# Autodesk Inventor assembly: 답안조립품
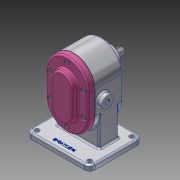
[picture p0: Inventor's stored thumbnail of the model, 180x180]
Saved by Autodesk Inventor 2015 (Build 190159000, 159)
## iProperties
Created: 2020-09
Part Number: 답안조립품
Document SubType Name: Assembly
Designer: Administrator
Author: Administrator
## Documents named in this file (11)
- C:\Users\Administrator\Desktop\700906V1016\답안조립품.iam
- C:\Users\Administrator\Desktop\700906V1016\본체.ipt
- C:\Users\Administrator\Desktop\700906V1016\메인축.ipt
- C:\Users\Administrator\Desktop\700906V1016\서브축.ipt
- C:\Users\Administrator\Desktop\700906V1016\베어링부시.ipt
- C:\Users\Administrator\Desktop\700906V1016\오일 실 16 28 7.ipt
- C:\Users\Administrator\Desktop\700906V1016\키 6 x 6 x 18.ipt
- C:\Users\Administrator\Desktop\700906V1016\스퍼기어.ipt
- C:\Users\Administrator\Desktop\700906V1016\개스킷.ipt
- C:\Users\Administrator\Desktop\700906V1016\커버.ipt
- C:\Users\Administrator\Desktop\700906V1016\볼트 M5.ipt
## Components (1 placed, 1 different names)
1. 개스킷:1
